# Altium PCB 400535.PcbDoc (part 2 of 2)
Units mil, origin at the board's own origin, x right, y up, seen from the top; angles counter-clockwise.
Board outline 2125.98 x 2500 mil, 4 copper layers (Top Layer, Mid-Layer 1, Mid-Layer 2, Bottom Layer), stack 93.792 mil thick; 80 components, 40 nets, 250 pads, 682 vias.
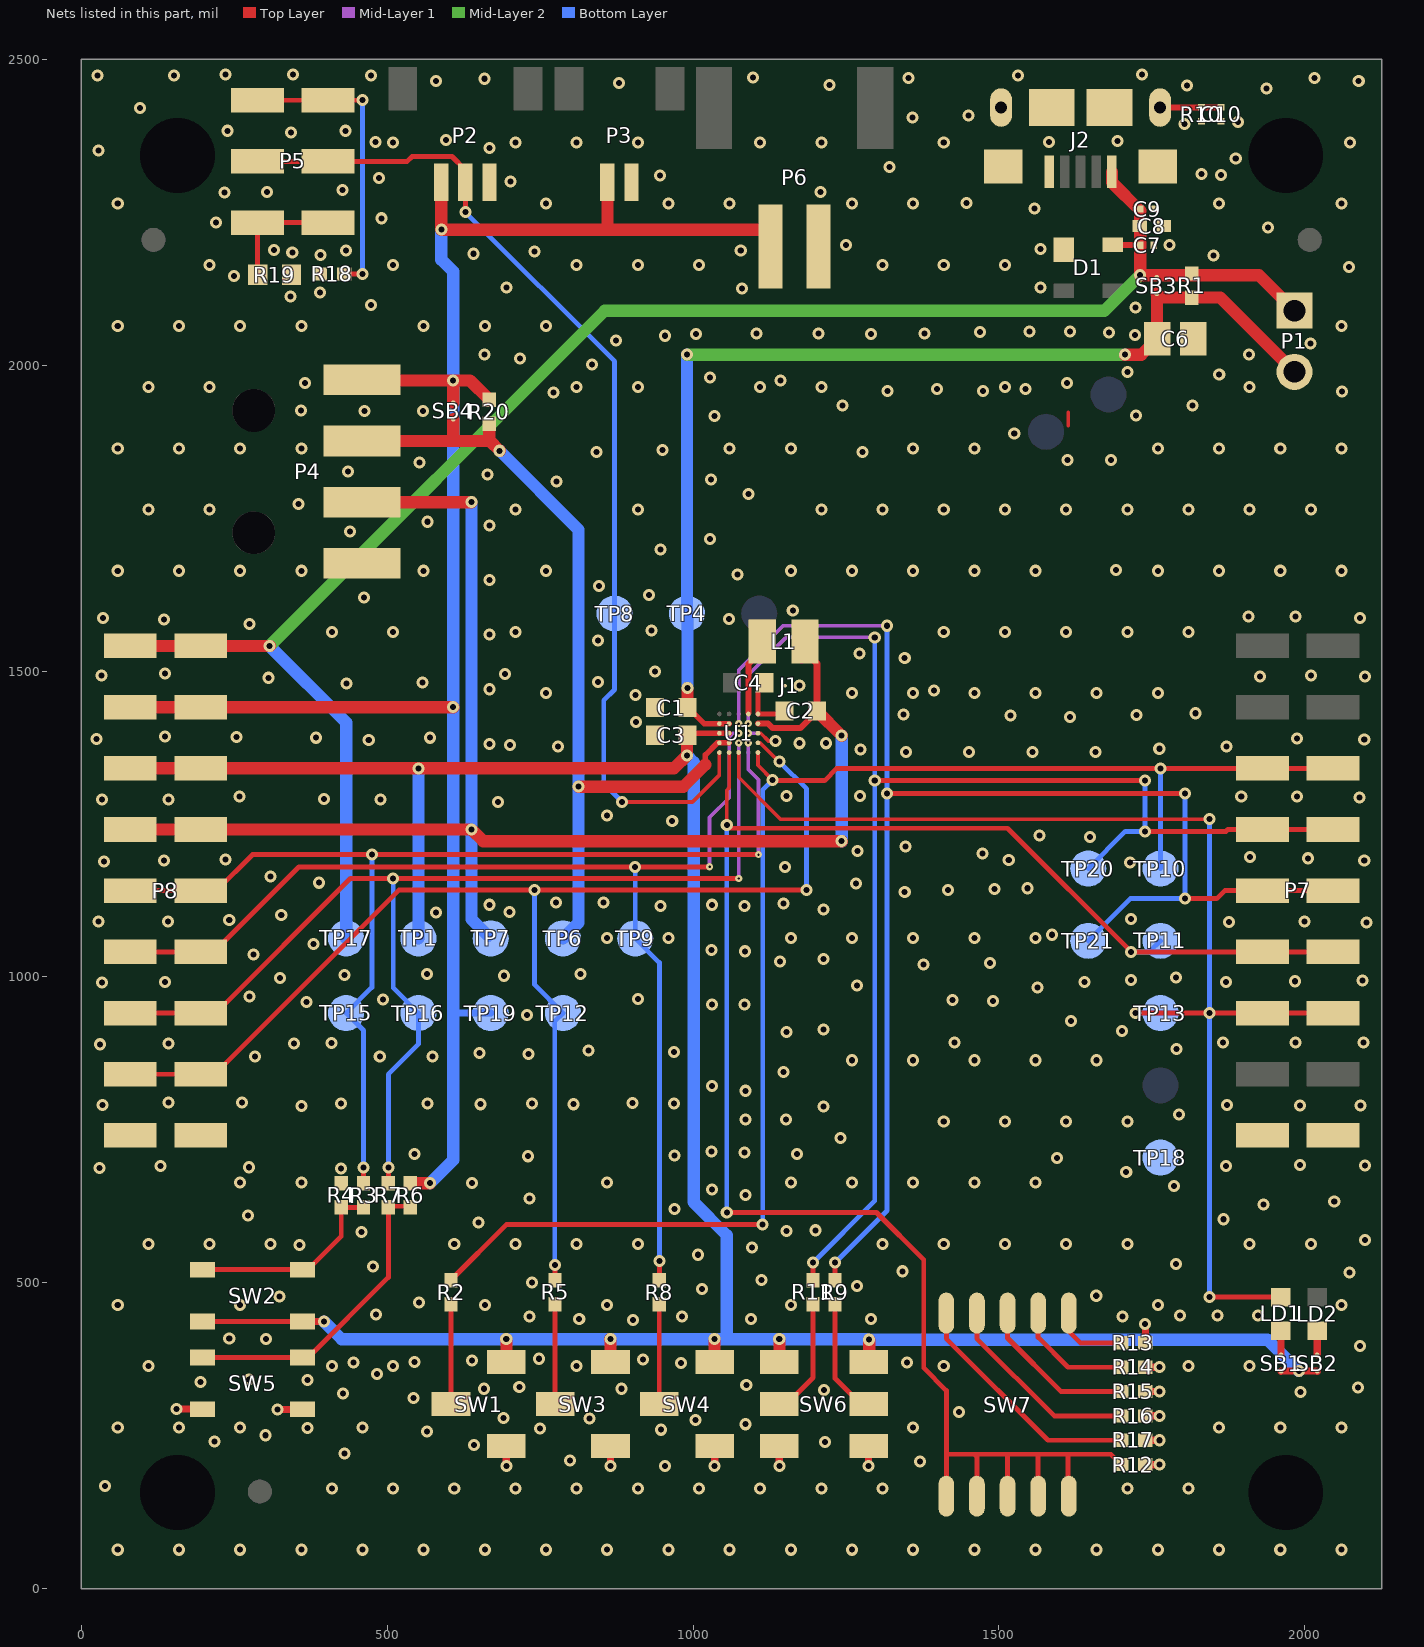
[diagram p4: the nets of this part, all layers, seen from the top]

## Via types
v1: diameter 19.68, hole 9.84, Top Layer to Bottom Layer, tented both sides, 673 vias
v2: diameter 11.81, hole 3.94, Top Layer to Mid-Layer 1, tented top, 8 vias
v3: diameter 11.81, hole 3.94, Top Layer to Mid-Layer 1, tented both sides, 1 vias

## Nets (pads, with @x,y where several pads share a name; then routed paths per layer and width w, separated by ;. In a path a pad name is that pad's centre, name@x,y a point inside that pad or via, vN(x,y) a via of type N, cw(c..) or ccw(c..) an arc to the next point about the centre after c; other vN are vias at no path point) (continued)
ERR: LD1.1 P7.7 TP13.1 U1.E3 | length 2099.9
  Top Layer w5.91: U1.E3@1074.62,1366.81 1074.62,1326.38 1143,1258 v1(1844,1258)
  Top Layer w8: v1(1723,941) P7.7@1930.51,941 P7.7@2045.87,941 ; v1@1844,476.81 LD1.1@1960.87,476.81
  Bottom Layer w8: v1(1723,941) TP13.1@1764,940.95 TP13.1@1764,940.95 ; v1(1844,477) v1(1844,1258)
  other v1: 1844,941
GND: C1.1 C3.1 C6.1 C7.2 C8.2 C9.2 C10.2 D1.1 J1.2 J2.5 P2.1 P3.1 P4.4 P6.1 P7.9 P8.9 R4.2 R10.2 R12.1 R13.1 R14.1 R15.1 R16.1 R17.1 R18.1 R19.1 SW1.3 SW3.3 SW4.3 SW5.2 SW6.1 SW6.4 TP18.1 U1.C4 U1.C5 | length 462
  Top Layer w5.91: 1613,1901 1613,1923
  Top Layer w6: U1.C5@1106.12,1398.31 1110.69,1398.31 1123.44,1385.56 v1(1134.58,1385.56)
  Top Layer w12: v1(156,294) 197.72,294 SW5.2@198.31,293.4 ; v1(321,293) 361.3,293 SW5.2@361.7,293.4 ; v1(695,200.81) SW1.3@695,233.11 ; v1(865.14,200.81) SW3.3@865.14,233.11 ; v1(1035.28,200.81) SW4.3@1035.28,233.11 ; v1(1141.17,200.81) SW6.4@1141.17,233.11 ; v1(1286.83,200.81) SW6.1@1286.83,233.11 ; v1(1739,433) 1739.37,432.63 R13.1@1739.37,402 ; R12.1@1739.37,203 v1(1762.74,203) ; R17.1@1739.37,242.8 v1(1762.74,242.8) ; R16.1@1739.37,282.6 v1(1762.74,282.6) ; R15.1@1739.37,322.4 v1(1762.74,322.4) ; R14.1@1739.37,362.2 v1(1762.74,362.2)
  Mid-Layer 1 w6: v3(1090.37,1398.31) 1103.69,1398.31
  other v1: 59.75,63.87 159.75,63.87 259.75,63.87 359.75,63.87 459.75,63.87 559.75,63.87 659.75,63.87 759.75,63.87 859.75,63.87 959.75,63.87 1059.75,63.87 1159.75,63.87 1259.75,63.87 1359.75,63.87 1459.75,63.87 1559.75,63.87 1659.75,63.87 1759.75,63.87 1859.75,63.87 1959.75,63.87 2059.75,63.87 409.75,163.87 509.75,163.87 609.75,163.87 709.75,163.87 809.75,163.87 909.75,163.87 1009.75,163.87 1109.75,163.87 1209.75,163.87 1309.75,163.87 1709.75,163.87 1809.75,163.87 39,168 954,201 1371,208 799,210 430,221 642,235 1216,240 218,241 301,251 565,257 948,260 750,262 370,263 59.75,263.87 159.75,263.87 259.75,263.87 459.75,263.87 1359.75,263.87 1859.75,263.87 1959.75,263.87 2059.75,263.87 1086,269 1004,276 831,278 690,279 1435,289 543,312 428,319 1993,322 1214,325 658,327 883,327 2087,329 716,330 1087,333 195,338 370,341 274,342 483.6,351.4 109.75,363.87 409.75,363.87 509.75,363.87 809.75,363.87 1409.75,363.87 1809.75,363.87 1909.75,363.87 980,369 445,370 1350,370 545,371 639,373 918,375 748,376 2090,397 302,408 242,409 902,439 814,441 1095,441 1291,441 733,445 982,445 1702,445 1796,447 1857,447 1923,447 482,448 59.75,463.87 259.75,463.87 659.75,463.87 859.75,463.87 1159.75,463.87 1759.75,463.87 2059.75,463.87 552,468 324,478 1659,479 1015,490 1268,495 737,501 1112,505 2073,517 1342,519 477,527 1789,531 1008,546 1096,558 357,562 109.75,563.87 209.75,563.87 309.75,563.87 609.75,563.87 709.75,563.87 809.75,563.87 909.75,563.87 1309.75,563.87 1409.75,563.87 1509.75,563.87 1609.75,563.87 1709.75,563.87 1909.75,563.87 2009.75,563.87 2098,570 458,583 1153,585 1200,586 649,599 1867,604 273,610 970,621 1932,628 2048,633 733,638 1086,644 1031,653 1786,658 639,663 259.75,663.87 359.75,663.87 859.75,663.87 1159.75,663.87 1259.75,663.87 1359.75,663.87 1459.75,663.87 1559.75,663.87 1708,681 425,687 30,688 274,689 130,691 1871,691 2098,692 1992,693 1595,704 730,707 970,708 545,711 1170,711 1084,713 1030,715 1241,737 1409.75,763.87 1509.75,763.87 1609.75,763.87 1709.75,763.87 1086,767 1152,767 1794,775 1213,788 360,789 1992,790 2091,790 35,791 1873,791 653,792 805,792 425,793 566,793 737,793 969,793 901,794 143,795 263,795 1086,814 1031,822 1148,845 1259.75,863.87 1359.75,863.87 1459.75,863.87 1559.75,863.87 1659.75,863.87 284,870 488,870 574,870 731,874 651,876 969,877 829,880 1790,882 31,890 143,891 348,891 409,892 1427,893 1866,893 1985,893 2096,893 1153,910 1701,912 1213,914 1618,928 729,938 1031,955 1084,955 368,959 1490,961 1424,962 493,963 909.75,963.87 275,968 1563,983 1268,986 34,991 137,992 1640,992 1871,992 1984,993 2094,994 1716,995 325,998 1789,999 691,1002 430,1003 565,1005 816,1005 1377,1020 1485,1023 1142,1025 1213,1029 282,1037 1085,1042 1030,1044 380,1054 859.75,1063.87 959.75,1063.87 1159.75,1063.87 1259.75,1063.87 1359.75,1063.87 1459.75,1063.87 1559.75,1063.87 1587,1069 2101,1089 1876,1090 28,1091 142,1091 1999,1091 242,1093 1716,1095 327,1101 580,1105 700,1106 1213,1110 947,1116 1084,1116 667,1118 1031,1118 1148,1120 776,1122 854,1122 1346,1139 1417,1142 1493,1144 1547,1145 1266,1153 389,1154 309.75,1163.87 1150,1180 1714,1187 37,1189 135,1190 2097,1190 1516,1191 236,1192 2005,1194 1910,1196 1473,1202 1269,1206 1347,1213 1649,1229 1566,1231 966,1255 859.75,1263.87 681,1286 34,1290 143,1290 489,1290 397,1291 2089,1293 259,1295 1896,1295 1987,1295 1153,1296 1273,1296 1348,1368 1451.25,1368 1554.5,1368 1657.75,1368 1274,1372 1762,1373 779,1377 1872,1377 701,1379 667,1381 1174,1382 1217,1382 470,1387 2097,1388 25,1389 1987,1390 384,1391 570,1391 254,1392 137,1393 907,1417 1616,1425 1519,1427 1725,1428 1344,1429 1821,1431 906,1461 759.75,1463.87 1259.75,1463.87 1359.75,1463.87 1459.75,1463.87 1559.75,1463.87 1659.75,1463.87 1759.75,1463.87 1394,1468 667,1470.25 1174.03,1476.06 434,1480 558,1481 845,1482 306,1489 1927,1491 2098,1491 33,1493 2010,1493 693,1495 137,1496 938,1499 1346,1521 1272,1529 845,1550 667,1559.5 409.75,1563.87 509.75,1563.87 709.75,1563.87 1409.75,1563.87 1509.75,1563.87 1609.75,1563.87 1709.75,1563.87 1809.75,1563.87 932,1566 275,1577 135,1584 1059,1585 36,1587 2090,1587 1908,1589 1985,1589 1163,1599 462,1620 928,1624 846,1639 667,1648.75 1073,1658 59.75,1663.87 159.75,1663.87 259.75,1663.87 359.75,1663.87 559.75,1663.87 759.75,1663.87 1159.75,1663.87 1259.75,1663.87 1359.75,1663.87 1459.75,1663.87 1559.75,1663.87 1759.75,1663.87 1859.75,1663.87 1959.75,1663.87 2059.75,1663.87 1691,1665 947,1699 1028,1716 439,1728 667,1738 566,1744 109.75,1763.87 209.75,1763.87 709.75,1763.87 909.75,1763.87 1209.75,1763.87 1309.75,1763.87 1409.75,1763.87 1509.75,1763.87 1609.75,1763.87 1709.75,1763.87 1809.75,1763.87 1909.75,1763.87 2009.75,1763.87 355,1773 1091,1789 777,1810 1029,1813 664,1821 436,1826 553,1841 1612,1845 1683,1845 842,1858 1277,1858 950,1861 59.75,1863.87 159.75,1863.87 259.75,1863.87 359.75,1863.87 1059.75,1863.87 1159.75,1863.87 1359.75,1863.87 1459.75,1863.87 1759.75,1863.87 1859.75,1863.87 1959.75,1863.87 2059.75,1863.87 1525,1888 1035,1917 1724,1918 463,1925 559,1925 359,1926 1244,1934 1816,1934 772,1955 2061,1957 1318,1958 1474,1958 1399,1961 1543,1961 109.75,1963.87 209.75,1963.87 809.75,1963.87 909.75,1963.87 1109.75,1963.87 1209.75,1963.87 1509.75,1963.87 1909.75,1963.87 366,1971 1611,1971 1143,1975 1028,1980 1860,1985 1710,1989 835,2001 717,2011 659,2017 1909,2017 2009,2035 874,2040 954,2048 1722,2049 1005,2051 1291,2051 1104,2052 1205,2052 1378,2052 1680,2053 1469,2054 1550,2055 1616,2055 59.75,2063.87 159.75,2063.87 259.75,2063.87 359.75,2063.87 559.75,2063.87 659.75,2063.87 759.75,2063.87 2059.75,2063.87 1723,2094 474,2098 342,2112 390,2119 1080,2125 695,2127 1568,2127 250,2146 2072,2160 209.75,2163.87 509.75,2163.87 809.75,2163.87 909.75,2163.87 1009.75,2163.87 1309.75,2163.87 1409.75,2163.87 1509.75,2163.87 1851,2179 391,2180 641,2182 345,2184 741,2186 433,2187 1078,2187 315,2188 1568,2190 1250,2196 1779,2196 1940,2225 220,2233 491,2240 1558,2256 59.75,2263.87 759.75,2263.87 959.75,2263.87 1059.75,2263.87 1259.75,2263.87 1359.75,2263.87 1859.75,2263.87 2059.75,2263.87 1447,2265 234,2282 304,2283 1208,2283 427,2286 702,2300 487,2306 946,2310 1863,2311 1831,2312 1321,2324 1887,2338 28,2351 667,2355 509.75,2363.87 709.75,2363.87 809.75,2363.87 909.75,2363.87 1109.75,2363.87 1209.75,2363.87 1409.75,2363.87 2074,2364 481,2365 1582,2365 1694,2366 596,2368 343,2380 239,2383 432,2383 1803,2394 1891,2397 1359,2405 1450,2408 96,2420 1937,2452 1807,2457 1223,2458 879,2461 580,2464 2088,2464 659,2468 1352,2469 2016,2469 1098,2470 27,2473 152,2473 474,2473 1531,2473 236,2475 346,2475 1734,2475
ICHG: P7.6 R12.2 SW7.6 SW7.7 SW7.8 SW7.9 SW7.10 TP11.1 U1.E2 | length 3211.4
  Top Layer w5.91: v1(1055.13,1248.13) 1055.13,1305.25 1058.87,1309 U1.E2@1058.87,1366.81
  Top Layer w8: v1(1055.13,615.13) 1299.87,615.13 1377,538 1377,361 1414,324 1414,221 ; v1(1055.13,1248.13) 1060.25,1243 1514,1243 v1(1716,1041) P7.6@1930.51,1041 P7.6@2045.87,1041 ; SW7.6@1414,151.39 1414,221 ; SW7.7@1464,151.39 1464,216 1460,220 ; SW7.8@1514,151.39 1514,220 ; SW7.9@1564,151.39 1564,219 1563,220 ; SW7.10@1614,151.39 1612.94,152.46 1612.94,219.94 1613,220 ; R12.2@1700,203 1683,220 1613,220 ; 1414,221 1415,220 1460,220 ; 1460,220 1514,220 ; 1514,220 1563,220 ; 1563,220 1613,220
  Bottom Layer w8: v1(1055.13,615.13) v1(1055.13,1248.13) ; v1(1716,1041) 1745.94,1041 TP11.1@1764,1059.06
ISET: P8.8 R5.2 TP12.1 U1.D5 | length 2172.3
  Top Layer w5.91: U1.D5@1106.12,1382.56 1109.44,1382.56 1140,1352 v1(1141,1352)
  Top Layer w8: P8.8@80.12,841 P8.8@195.47,841 218,841 519,1142 v1(741,1142) v1(1185.37,1142) ; R5.2@774.59,504.69 v1(774.59,529.59)
  Bottom Layer w8: v1@741,1146 v1(741,1142) 741,987.4 TP12.1@787.4,941 774,927.6 774,530.17 v1(774.59,529.59) ; v1(1141,1352) 1185.67,1307.33 v1@1185.67,1142
MODE: P7.3 R2.2 TP10.1 U1.E5 | length 2423.6
  Top Layer w5.91: U1.E5@1106.12,1366.81 1106.12,1345.88 v1(1130,1322)
  Top Layer w8: R2.2@604.45,504.69 694.87,595.11 v1(1113.89,595.11) ; v1(1130,1322) 1131,1321 1215,1321 1235,1341 v1(1764,1341) P7.3@1930.51,1341 P7.3@2045.87,1341
  Bottom Layer w8: v1(1113.89,595.11) 1113.89,1305.89 v1(1130,1322) ; TP10.1@1764,1177.17 v1(1764,1341)
NetC10_1: C10.1 J2.6@1503.43,2420.96 J2.6@1507.37,2324.51 J2.6@1586.11,2420.96 J2.6@1680.6,2420.96 J2.6@1759.34,2324.51 J2.6@1763.27,2420.96 R10.1 | length 99.8
  Top Layer w10: J2.6@1763.27,2420.96 1763.53,2421.22 C10.1@1863,2421.22
NetL1_1: L1.1 U1.A4 | length 129.5
  Top Layer w9.84: U1.A4@1090.37,1431.77 1090.37,1511.37 1122.52,1543.52 L1.1@1122.52,1548
NetLD1_2: LD1.2 SB1.2 | length 39.6
  Top Layer w12: LD1.2@1960.87,421.81 1960.87,382.43 SB1.2@1961,382.3
NetLD2_2: LD2.2 SB2.2 | length 39.5
  Top Layer w12: LD2.2@2019.92,421.81 2019.92,382.38 SB2.2@2020,382.3
NetP5_1: P5.1 R19.2 | length 200.5
  Top Layer w8: R19.2@288.44,2148 288.44,2232.49 P5.1@288,2232.93 P5.1@403.35,2232.93
NetP5_3: P5.3 R18.2 | length 486.3
  Top Layer w8: P5.3@288,2432.93 P5.3@403.35,2432.93 v1(459.93,2432.93) ; R18.2@429.68,2149 v1(460,2149)
  Bottom Layer w8: v1(459.93,2432.93) v1(459.93,2432.93) v1(460,2149)
NetR2_1: R2.1 SW1.2 | length 163.3
  Top Layer w8: SW1.2@604.45,302.01 R2.1@604.45,465.31
NetR3_1: R3.1 R4.1 SW2.1 | length 333
  Top Layer w8: SW2.1@198.31,521.57 370.58,521.58 425,576 R4.1@425,623.31 R3.1@461.42,623.31
NetR5_1: R5.1 SW3.2 | length 163.3
  Top Layer w8: SW3.2@774.59,302.01 R5.1@774.59,465.31
NetR6_1: R6.1 R7.1 SW5.1 | length 510.3
  Top Layer w8: SW5.1@198.31,378.05 SW5.1@361.7,378.05 371.05,378.05 501.96,508.96 501.96,625.31 R6.1@538,625.31
NetR8_1: R8.1 SW4.2 | length 163.3
  Top Layer w8: SW4.2@944.72,302.01 R8.1@944.72,465.31
NetR9_1: R9.1 SW6.2 | length 193.5
  Top Layer w8: R9.1@1232,465.31 1232,344 1273.99,302.01 SW6.2@1286.83,302.01
NetR11_1: R11.1 SW6.5 | length 193
  Top Layer w8: SW6.5@1141.17,302.01 1153.01,302.01 1196,345 R11.1@1196,465.31
NetR13_2: R13.2 SW7.1 | length 123.5
  Top Layer w8: SW7.1@1614,450.61 1614,421 1633,402 R13.2@1700,402
NetR14_2: R14.2 SW7.2 | length 195.8
  Top Layer w8: SW7.2@1564,450.61 1564,411 1612.8,362.2 R14.2@1700,362.2
NetR15_2: R15.2 SW7.3 | length 262.9
  Top Layer w8: SW7.3@1514,450.61 1514,410 1601.6,322.4 R15.2@1700,322.4
NetR16_2: R16.2 SW7.4 | length 330
  Top Layer w8: SW7.4@1464,450.61 1464,409 1590.4,282.6 R16.2@1700,282.6
NetR17_2: R17.2 SW7.5 | length 396.4
  Top Layer w8: SW7.5@1414,450.61 1414,409 1580.2,242.8 R17.2@1700,242.8
NTC: P2.2 P5.2 TP8.1 U1.E1 | length 1720.4
  Top Layer w5.91: v1(884,1286) 999,1286 1043.13,1330.13 U1.E1@1043.13,1366.81
  Top Layer w8: P5.2@288,2332.93 P5.2@403.35,2332.93 532.93,2332.93 541,2341 606,2341 628,2319 P2.2@628,2299.02 v1(628,2250)
  Bottom Layer w8: v1(628,2250) 871.89,2006.11 871.89,1941 871.89,1469.89 854,1452 854,1316 v1(884,1286)
PVSS: C2.1 C4.1 J1.1 U1.A5 | length 101
  Top Layer w7.87: C4.1@1116.94,1480.98 1106.12,1470.16 U1.A5@1106.12,1429.8 1144.5,1429.8 C2.1@1149.42,1434.72
SHPACT: P8.5 R3.2 TP15.1 U1.D4 | length 1807.2
  Top Layer w8: P8.5@80.12,1141 P8.5@195.47,1141 221,1141 280,1200 v1(475,1200) v2(1107,1200) ; R3.2@461.42,662.69 v1(461.42,688.96)
  Mid-Layer 1 w5.91: v2(1090.37,1382.56) 1090.37,1339 1107,1322.37 v2(1107,1200)
  Bottom Layer w8: v1(461.42,688.96) 461.42,912.65 TP15.1@433.07,941 475,982.93 v1(475,1200)
SHPHLD: P8.7 R7.2 TP16.1 U1.D3 | length 1847
  Top Layer w8: P8.7@80.12,941 P8.7@195.47,941 220,941 440,1161 v1(510,1161) v2(1074.62,1161) ; R7.2@501.96,662.69 v1(501.96,688.96)
  Mid-Layer 1 w5.91: v2(1074.62,1161) v2(1074.62,1382.56)
  Bottom Layer w8: v1(501.96,688.96) 501.96,840.96 551.18,890.18 TP16.1@551.18,941 510,982.18 v1(510,1161) v1@510,1165
VBAT: P2.3 P3.2 P4.1 P6.2 P8.2 R6.2 R20.2 SB4.2 TP19.1 | length 3180.9
  Top Layer w20: P8.2@80.12,1441 P8.2@195.47,1441 v1(608,1441) ; P4.1@458.01,1975 v1(608,1975) ; R6.2@538,662.69 538.31,663 v1(570,663) ; v1(588.63,2221.37) 862,2221.37 ; v1@588.63,2224.37 P2.3@588.63,2299.02 ; SB4.2@608,1938.3 v1(608,1975) ; R20.2@667,1943.69 635.69,1975 v1(608,1975) ; P3.2@860.05,2299.02 860.05,2223.31 862,2221.37 ; P6.2@1126.63,2193.7 1126.63,2221.37 862,2221.37
  Bottom Layer w12: 608,941 TP19.1@669.29,941
  Bottom Layer w20: v1(570,663) 608,701 608,941 v1(608,1975) 608,2153 588.63,2172.37 v1(588.63,2221.37)
VBAT_HF: P4.2 R20.1 SB4.1 TP6.1 U1.D1 U1.D2 | length 1438
  Top Layer w9: 1020,1347 1020,1363 1039.56,1382.56 U1.D1@1043.13,1382.56 U1.D2@1058.87,1382.56
  Top Layer w20: P4.2@459.01,1876 608,1876 ; SB4.1@608,1911.7 608,1876 ; R20.1@667,1904.31 667,1877 668,1876 ; v1(684,1860) 668,1876 ; v1(813,1311) 984,1311 1020,1347 ; 608,1876 668,1876
  Bottom Layer w20: v1(684,1860) 813,1731 v1@813,1315 ; TP6.1@787.4,1062.99 813,1088.59 v1(813,1311)
VBUS: C7.1 C8.1 C9.1 D1.4 J2.1 P1.1 P8.1 R1.2 SB3.1 TP17.1 | length 2940.5
  Top Layer w10: D1.4@1686.35,2196.4 1686.76,2196 C7.1@1730.78,2196
  Top Layer w20: P8.1@80.12,1541 P8.1@195.47,1541 v1(308,1541) ; J2.1@1684.53,2315.65 1684.53,2298.47 1730.78,2252.22 1730.78,2227 C7.1@1730.78,2196 v1(1730.78,2147.22) 1731,2147 1758,2147 1815,2147 1925,2147 P1.1@1983,2089 P1.1@1982.7,2088.7
  Mid-Layer 2 w20: v1(308,1541) 855.7,2088.7 1672.26,2088.7 v1(1730.78,2147.22)
  Bottom Layer w20: v1(308,1541) 433.07,1415.93 TP17.1@433.07,1062.99
VBUS_HF: C1.2 C6.2 P1.2 R1.1 SB3.2 TP4.1 U1.B1 U1.B2 | length 1786.3
  Top Layer w9: C1.2@990.96,1440.3 991.7,1440.3 1017.94,1414.06 U1.B1@1043.13,1414.06 U1.B2@1058.87,1414.06
  Top Layer w20: C1.2@990.96,1440.3 v1(990.96,1471.96) ; v1(1706,2017) 1732.47,2017 C6.2@1758.47,2043 SB3.2@1758.47,2116.24 ; SB3.2@1758,2116.72 SB3.2@1758.47,2116.24 ; P1.2@1983,1989 1861.67,2110.33 R1.1@1815,2110.33 1764.38,2110.33 SB3.2@1758.47,2116.24
  Mid-Layer 2 w20: v1(990,2017) v1(1706,2017)
  Bottom Layer w20: v1(990,2017) TP4.1@990,1594 990.96,1593.04 v1(990.96,1471.96)
VOUTB: C2.2 L1.2 P4.3 P8.4 TP7.1 U1.B5 | length 2530.9
  Top Layer w9.84: U1.B5@1106.12,1414.06 1122.85,1414.05 1129.74,1407.17 1176,1407.17 C2.2@1202.57,1433.74 ; L1.2@1182.84,1532.16 L1.2@1182.84,1548
  Top Layer w12: L1.2@1182.84,1532.16 1202.57,1512.43 C2.2@1202.57,1434.72
  Top Layer w20: P8.4@80.12,1241 P8.4@195.47,1241 v1(638,1241) 657,1222 v1(1243,1222) ; P4.3@459.01,1776 v1(638,1776) ; C2.2@1202.57,1434.72 v1(1243,1394.3)
  Bottom Layer w20: v1(638,1776) v1(638,1241) 638,1094.28 TP7.1@665,1067.28 ; v1(1243,1222) v1(1243,1394.3)
VOUTBSET0: P7.4 R11.2 TP20.1 U1.B4 | length 2355
  Top Layer w8: R11.2@1196,504.69 v1(1196,533) ; v1(1297,1321) v1(1739,1321) ; v1(1739,1238) 1871,1238 1874,1241 P7.4@1930.51,1241 P7.4@2045.87,1241
  Mid-Layer 1 w6: v2(1090.37,1414.06) 1090.37,1493.37 1152,1555 v1(1297,1555)
  Bottom Layer w8: v1(1196,533) 1297,634 v1(1297,1321) v1(1297,1555) ; TP20.1@1645.89,1177.17 1706.72,1238 v1(1739,1238) v1(1739,1321)
VOUTBSET1: P7.5 R9.2 TP21.1 U1.B3 | length 2557.4
  Top Layer w8: R9.2@1232,504.69 v1(1232,533) ; v1(1317,1300) v1(1804,1300) ; v1(1804,1128) 1856,1128 1869,1141 P7.5@1930.51,1141 P7.5@2045.87,1141
  Mid-Layer 1 w6: v2(1074.62,1414.06) 1074.62,1501.62 1147,1574 v1(1317,1574)
  Bottom Layer w8: v1(1232,533) 1317,618 v1(1317,1300) v1(1317,1574) ; TP21.1@1645.89,1059.06 1714.83,1128 v1(1804,1128) v1(1804,1300)
VSYS: C3.2 P8.3 SB1.1 SB2.1 SW1.1 SW2.2 SW3.1 SW4.1 SW6.3 SW6.6 TP1.1 U1.C1 U1.C2 | length 4350.8
  Top Layer w7.87: C3.2@990,1394.06 C3.2@990.96,1395.02 C3.2@994.24,1398.31
  Top Layer w8: SW2.2@198.31,436.93 SW2.2@361.7,436.93
  Top Layer w9: C3.2@994.24,1398.31 U1.C1@1043.13,1398.31 U1.C2@1058.87,1398.31
  Top Layer w12: SW2.2@361.7,436.93 v1(396.93,436.93) ; SB1.1@1961,355.7 1961.3,356 v1(1990,356) 2019.7,356 SB2.1@2020,355.7
  Top Layer w20: P8.3@80.12,1341 P8.3@195.47,1341 v1@551,1341 ; v1(551.18,1340.82) v1@551,1341 ; v1(694.72,408) 695,407.72 SW1.1@695,370.91 ; v1(864.86,408) 865.14,407.72 SW3.1@865.14,370.91 ; C3.2@990,1394.06 v1(990,1362) 969,1341 v1@551,1341 ; v1(1035,408) 1035.28,407.72 SW4.1@1035.28,370.91 ; v1(1140.89,408) 1141.17,407.72 SW6.6@1141.17,370.91 ; v1(1287.72,407.09) 1288,406.82 SW6.3@1288,370
  Bottom Layer w20: v1(396.93,436.93) 425.85,408 v1(694.72,408) v1(864.86,408) v1(1035,408) 1055,408 ; TP1.1@551.18,1062.99 v1(551.18,1340.82) ; v1(990,1362) 1001,1351 1001,632 1055,578 1055,408 ; v1(1990,356) 1938.91,407.09 v1(1287.72,407.09) 1286.82,408 v1(1140.89,408) 1055,408
VTERM: P8.6 R8.2 TP9.1 U1.C3 | length 1935.7
  Top Layer w8: P8.6@80.12,1041 P8.6@195.47,1041 217,1041 356,1180 v1(905.51,1180) v2(1027,1180) ; R8.2@944.72,504.69 945,504.96 v1(945,536)
  Mid-Layer 1 w6: v2@1027,1184 1027,1261 1059,1293 1059,1392 1065.31,1398.31 v2(1074.62,1398.31)
  Bottom Layer w8: v1(905.51,1180) TP9.1@905.51,1062.99 945,1023.5 v1(945,536)
pads on no net: Fid1.0 Fid2.0 Fid3.0 J2.4 J2.6@1503.43,2420.96 J2.6@1763.27,2420.96 P2.0 P3.0 P4.0 P6.0
copper on no net:
  other v1: 1633.35,2368.31

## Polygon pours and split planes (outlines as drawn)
GND on Mid-Layer 1 "Mid_Layer_1-GND" (solid, remove dead copper, pour order 7): 0,0 0,2500 2125.98,2500 2125.98,0
GND on Mid-Layer 2 "Mid_Layer_2-GND" (solid, remove dead copper, pour order 9): 0,0 0,2500 2125.98,2500 2125.98,0
GND on Top Layer "Top_Layer-GND" (solid, remove dead copper, pour order 8): 0,0 0,2500 2125.98,2500 2125.98,0
GND on Bottom Layer "Bottom_Layer-GND" (solid, remove dead copper, pour order 6): 0,0 0,2500 2125.99,2500 2125.98,0

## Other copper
Top Layer:
  rectangle net PVSS: 1107.1,1428.82 1156.31,1496.73
  pour cut-out: 1167.14,1492.79 1167.14,1461.3 1187.81,1461.3 1187.81,1492.79
  pour cut-out: 1118.87,1594 1172.06,1594 1172.06,1504.48 1118.93,1504.48
  pour cut-out: 1937.84,391.83 1937.84,445 2044.16,445 2044.16,391.91
  pour cut-out: 1109.56,1455.89 1109.56,1440.14 1125.31,1440.14 1125.31,1455.89
Mid-Layer 1:
  pour cut-out: 2040.54,391.5 2000.36,391.5 2000.36,346.5 2040.2,346.5
  pour cut-out: 1778.54,2152.52 1738.36,2152.52 1738.36,2107.52 1778.2,2107.52
  pour cut-out: 628,1902.93 628,1949 588,1949 588,1903.24
  pour cut-out: 1981.17,391.5 1941,391.5 1941,346.5 1980.83,346.5
Bottom Layer:
  pour cut-out: 484,977 499,977 499,983
  pour cut-out: 473,850 499,850 499,848 487,836

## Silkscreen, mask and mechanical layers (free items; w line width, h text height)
Top Overlay:
  drawing of 57 lines, arcs and shapes, not listed
  text "NTC" at 130,2439 h60
  text "+" at 572,2227 h27
  text "-" at 652,2227 h27
  text "+" at 844,2227 h27
  text "-" at 883,2227 h27
  text "NTC" at 648,2166.14 h55 r90
  text "+" at 1110,2087 h27
  text "-" at 1192,2087 h27
  text "VBAT" at 645,1980.14 h55
  text "Current" at 732,1928.14 h55
  text "Measurement" at 732,1876.14 h55
  text "VBAT_HF" at 645,1822.14 h55
  text "VOUTB" at 645,1747.14 h55
  text "'.PCBRevision'" at 2100,1680 h25 r90
  text "'.PCBNumber'" at 2064.87,1678.64 h80 r90
  text "nPM1100-EK" at 1051.92,1666 h150
  text "GND" at 645,1651.14 h55
  text "VBUS" at 259,1519 h70
  text "D-" at 1796.25,1519 h70
  text "VBAT" at 259,1420.22 h70
  text "D+" at 1782.73,1420.22 h70
  text "VSYS" at 259,1319.76 h70
  text "MODE" at 1677.03,1319.76 h70
  text "VOUTB" at 259,1219.3 h70
  text "VOUTBSET0" at 1484.76,1219.3 h70
  text "ICHG" at 609,1156 h60
  text "Charge Current" at 820.5,1156 h60
  text "R_ICHG" at 1248.15,1156 h60
  text "SHPACT" at 259,1118.83 h70
  text "VOUTBSET1" at 1491.87,1118.83 h70
  text "1" at 698,1081 h75
  text "0R" at 1294.51,1081 h75
  text "400mA" at 928.28,1080.12 h75
  text "VTERM" at 259,1020.06 h70
  text "ICHG" at 1708.86,1018.37 h70
  text "2" at 698,974.4 h75
  text "1k" at 1294.51,974.4 h75
  text "250mA" at 928.28,973.97 h75
  text "SHPHLD" at 259,919.59 h70
  text "ERR" at 1730.08,919.59 h70
  text "3" at 698,869 h75
  text "2.7k" at 1294.51,869 h75
  text "150mA" at 928.28,867.82 h75
  text "ISET" at 259,819.13 h70
  text "CHG" at 1724.95,819.13 h70
  text "4" at 698,762.46 h75
  text "12k" at 1294.51,762.4 h75
  text "50mA" at 928.28,761.67 h75
  text "GND" at 259,718.67 h70
  text "GND" at 1724.25,718.67 h70
  text "5" at 698,657.27 h75
  text "20mA" at 928.28,656.4 h75
  text "27k" at 1294.51,656.4 h75
  text "ERR" at 1989,512 h60 r90
  text "CHG" at 2045,512 h60 r90
  text "1" at 1602,498.76 h70
  text "5" at 1406,498 h70
  text "4" at 1452,498 h70
  text "3" at 1502,498 h70
  text "2" at 1551,498 h70
  text "SHPACT" at 111,431 h50 r90
  text "OFF" at 1679,428.58 h70
  text "VSYS" at 411,335.69 h70
  text "GND" at 411,230.69 h70
  text "SHPHLD" at 111,230 h50 r90
  text "ON" at 1684,129.58 h70
  text "MODE" at 597.84,105 h50
  text "ISET" at 767.68,105 h50
  text "VTERM" at 937.68,104.46 h50
  text "VOUTBSET" at 1132,105 h50
  text "ICHG" at 1450,47.58 h70
  text "0   1" at 1168,47 h60
Bottom Overlay:
  drawing of 908 lines, arcs and shapes, not listed
Board Outline:
  the board outline again, w6
PCB Info:
  lines w5.51: 1043.13,1429.8 ccw(c1033.81,1429.8) 1040.4,1436.39 1035.39,1441.39 cw(c1074.97,1480.97) 1019,1480.97 1019,1620.58 cw(c1134,1620.58) 1052.68,1701.9 1249.1,1898.32 cw(c1330.42,1817) 1330.42,1932 1578.12,1932 ccw(c1578.12,1950.21) 1591,1937.33 ; 1058.87,1429.8 cw(c1060.68,1431.61) 1058.13,1431.61 1058.13,1435.21 ccw(c1046.87,1435.21) 1054.83,1443.17 1046,1452 cw(c1074.97,1480.97) 1034,1480.97 1034,1620.58 cw(c1134,1620.58) 1063.29,1691.29 1259.71,1887.71 cw(c1330.42,1817) 1330.42,1917 1578.12,1917 cw(c1578.12,1898.79) 1591,1911.67 ; 1591,1910.67 cw(c1606.29,1895.37) 1606.29,1917 1622.12,1917 cw(c1622.12,1898.79) 1635,1911.67 ; 1591,1938.33 ccw(c1606.29,1953.63) 1606.29,1932 1647.12,1932 ccw(c1647.12,1950.21) 1660,1937.33 ; 1633.35,2315.65 cw(c1620.57,2302.87) 1638.65,2302.87 1638.65,2196.02 cw(c1538.65,2196.02) 1609.36,2125.31 1605.65,2121.6 1611.21,2116.03 cw(c1540.5,2045.32) 1640.5,2045.32 1640.5,1611.92 ccw(c1755.5,1611.92) 1674.18,1530.6 1683.39,1521.39 ccw(c1764.01,1602.01) 1764.01,1488 1842.09,1488 cw(c1842.09,1388) 1912.8,1458.71 1930.51,1441 2045.87,1441 ; 1658.94,2315.65 ccw(c1671.73,2302.87) 1653.65,2302.87 1653.65,2195.73 ccw(c1753.65,2195.73) 1682.94,2125.02 1686.35,2121.6 1684.79,2120.03 ccw(c1755.5,2049.32) 1655.5,2049.32 1655.5,1611.92 ccw(c1755.5,1611.92) 1684.79,1541.21 1694,1532 ccw(c1764.01,1602.01) 1764.01,1503 1851.09,1503 ccw(c1851.09,1603) 1921.8,1532.29 1930.51,1541 2045.87,1541
  text "90ohm impedance / differential pair" at 595,1122 h60
Bottom Component Info:
  text "D_N" at 1644.72,1725 h60 r270
  text "NTC" at 831.72,1687 h60 r270
  text "VBUS_HF" at 945.72,1687.06 h60 r270
  text "DEC" at 1071.72,1687 h60 r270
  text "D_P" at 1532.72,1662 h60 r270
  text "VBUS" at 405.72,1145.06 h60 r270
  text "VSY" at 519.39,1145.06 h60 r270
  text "VOUTB" at 633.05,1145.06 h60 r270
  text "VBAT_HF" at 751.72,1145.06 h60 r270
  text "MODE" at 1713.94,1135.72 h60
  text "ICHG" at 1714,1017.72 h60
  text "VTERM" at 1713.94,899 h60
  text "ERR" at 1714,782 h60
  text "ISET" at 744.72,636 h60 r270
  text "VBAT" at 630,626.06 h60 r270
  text "SHPACT" at 393.72,506.04 h60 r270
  text "SHPHLD" at 514.72,506.04 h60 r270
  text "GND" at 1604.72,483 h60 r270
  text "CHG" at 1723.72,483 h60 r270

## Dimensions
2125.98,0 to 1968.5,2342.52 on Dimension
2125.98,0 to 1968.5,157.48 on Dimension
0,0 to 1968.5,157.48 on Dimension
0,0 to 157.48,157.48 on Dimension
2125.98,2500 to 2125.98,0 on Dimension
0,0 to 2125.98,0 on Dimension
